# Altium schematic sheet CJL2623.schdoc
size 127 x 101 mm
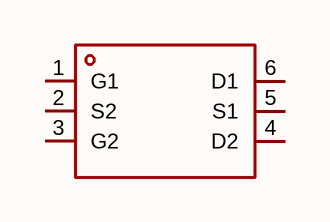
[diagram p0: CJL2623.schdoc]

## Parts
Q?  cjl2623  [SOT-23-6_L2.9-W1.6-P0.95-LS2.8-BR]  (value not drawn)

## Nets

Not connected (* = marked no-connect by the designer): Q? 1(G1) 2(S2) 3(G2) 4(D2) 5(S1) 6(D1)

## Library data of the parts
Q? = cjl2623: 数量:2个P沟道;漏源电压(Vdss):30V;连续漏极电流(Id):3A;导通电阻(RDS(on)):180mΩ@4.5V;耗散功率(Pd):350mW;阈值电压(Vgs(th)):3V;; Manufacturer: CJ(江苏长电/长晶); AddInBom: yes; ModelId: 18da8f6c14a34920b3e136b5c401a119; ModelName: SOT-23-6_L2.9-W1.6-H1.5-LS2.8-P0.95; ModelTransform: 110.73671,114.173,0,180,0,0,0.001,-0.003,0; Number: 2个P沟道; Drain to Source Voltage: 30V; Current - Continuous Drain(Id): 3A; Pd - Power Dissipation: 350mW; Gate Threshold Voltage (Vgs(th)): 3V; Gate Charge(Qg): 4.5nC@4.5V; Input Capacitance(Ciss): 240pF; Reverse Transfer Capacitance (Crss@Vds): 32pF; Type: P沟道; Output Capacitance(Coss): 42pF; Vgs: ±20V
